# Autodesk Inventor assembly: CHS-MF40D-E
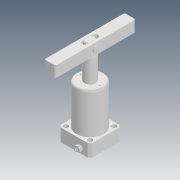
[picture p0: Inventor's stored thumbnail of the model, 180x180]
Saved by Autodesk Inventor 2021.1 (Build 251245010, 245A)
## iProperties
Created: 2019-04
Part Number: CHS-MF40D-E
Description: STEP AP203
Document SubType Name: Assembly
Designer: user
Title: chs-mf40d-e_asm.STEP
Revision Number: ÈÎºÎ
Sending System: SolidWorks 2017
Preprocessor: SwSTEP 2.0
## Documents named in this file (10)
- D:\Vault_2016\Projekty\Clamptek\Hydraulic\CHS\CHS-40\Inventor\CHS-MF40D-E\CHS-MF40D-E.iam
- D:\Vault_2016\Projekty\Clamptek\Hydraulic\CHS\CHS-40\Inventor\CHS-MF40D-E\CHS-MF40-11-30-BT.ipt
- D:\Vault_2016\Projekty\Clamptek\Hydraulic\CHS\CHS-40\Inventor\CHS-MF40D-E\CHS-40D-02-E_1.ipt
- D:\Vault_2016\Projekty\Clamptek\Hydraulic\CHS\CHS-40\Inventor\CHS-MF40D-E\CHS-TXF-01_3.ipt
- D:\Vault_2016\Projekty\Clamptek\Hydraulic\CHS\CHS-40\Inventor\CHS-MF40D-E\CHS-MF40-TXF-03_3.ipt
- D:\Vault_2016\Projekty\Clamptek\Hydraulic\CHS\CHS-40\Inventor\CHS-MF40D-E\CHS-MF40-TXF-02_3.ipt
- D:\Vault_2016\Projekty\Clamptek\Hydraulic\CHS\CHS-40\Inventor\CHS-MF40D-E\M6_3.ipt
- D:\Vault_2016\Projekty\Clamptek\Hydraulic\CHS\CHS-40\Inventor\CHS-MF40D-E\CHS-40D-01_7.ipt
- D:\Vault_2016\Projekty\Clamptek\Hydraulic\CHS\CHS-40\Inventor\CHS-MF40D-E\XIAO.ipt
- D:\Vault_2016\Projekty\Clamptek\Hydraulic\CHS\CHS-40\Inventor\CHS-MF40D-E\12ÖáÓÃµ²È¦.ipt
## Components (10 placed, 10 different names)
1. CHS-MF40-11-30-BT_1
2. CHS-40D-02-E_1_2
3. CHS-TXF-01_3_3
4. CHS-MF40-TXF-03_3_4
5. CHS-MF40-TXF-02_3_5
6. M6_3_6
7. CHS-40D-01_7_7
8. XIAO_8
9. 12ÖáÓÃµ²È¦_9
10. 12ÖáÓÃµ²È¦_10
